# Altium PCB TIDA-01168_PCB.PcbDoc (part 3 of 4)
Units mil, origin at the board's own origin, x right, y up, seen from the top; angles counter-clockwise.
Board outline 7874.02 x 8344.02 mil, 4 copper layers (Top Layer, Signal Layer 1, Signal Layer 2, Bottom Layer), stack 65.748 mil thick; 480 components, 223 nets, 1266 pads, 1791 vias.
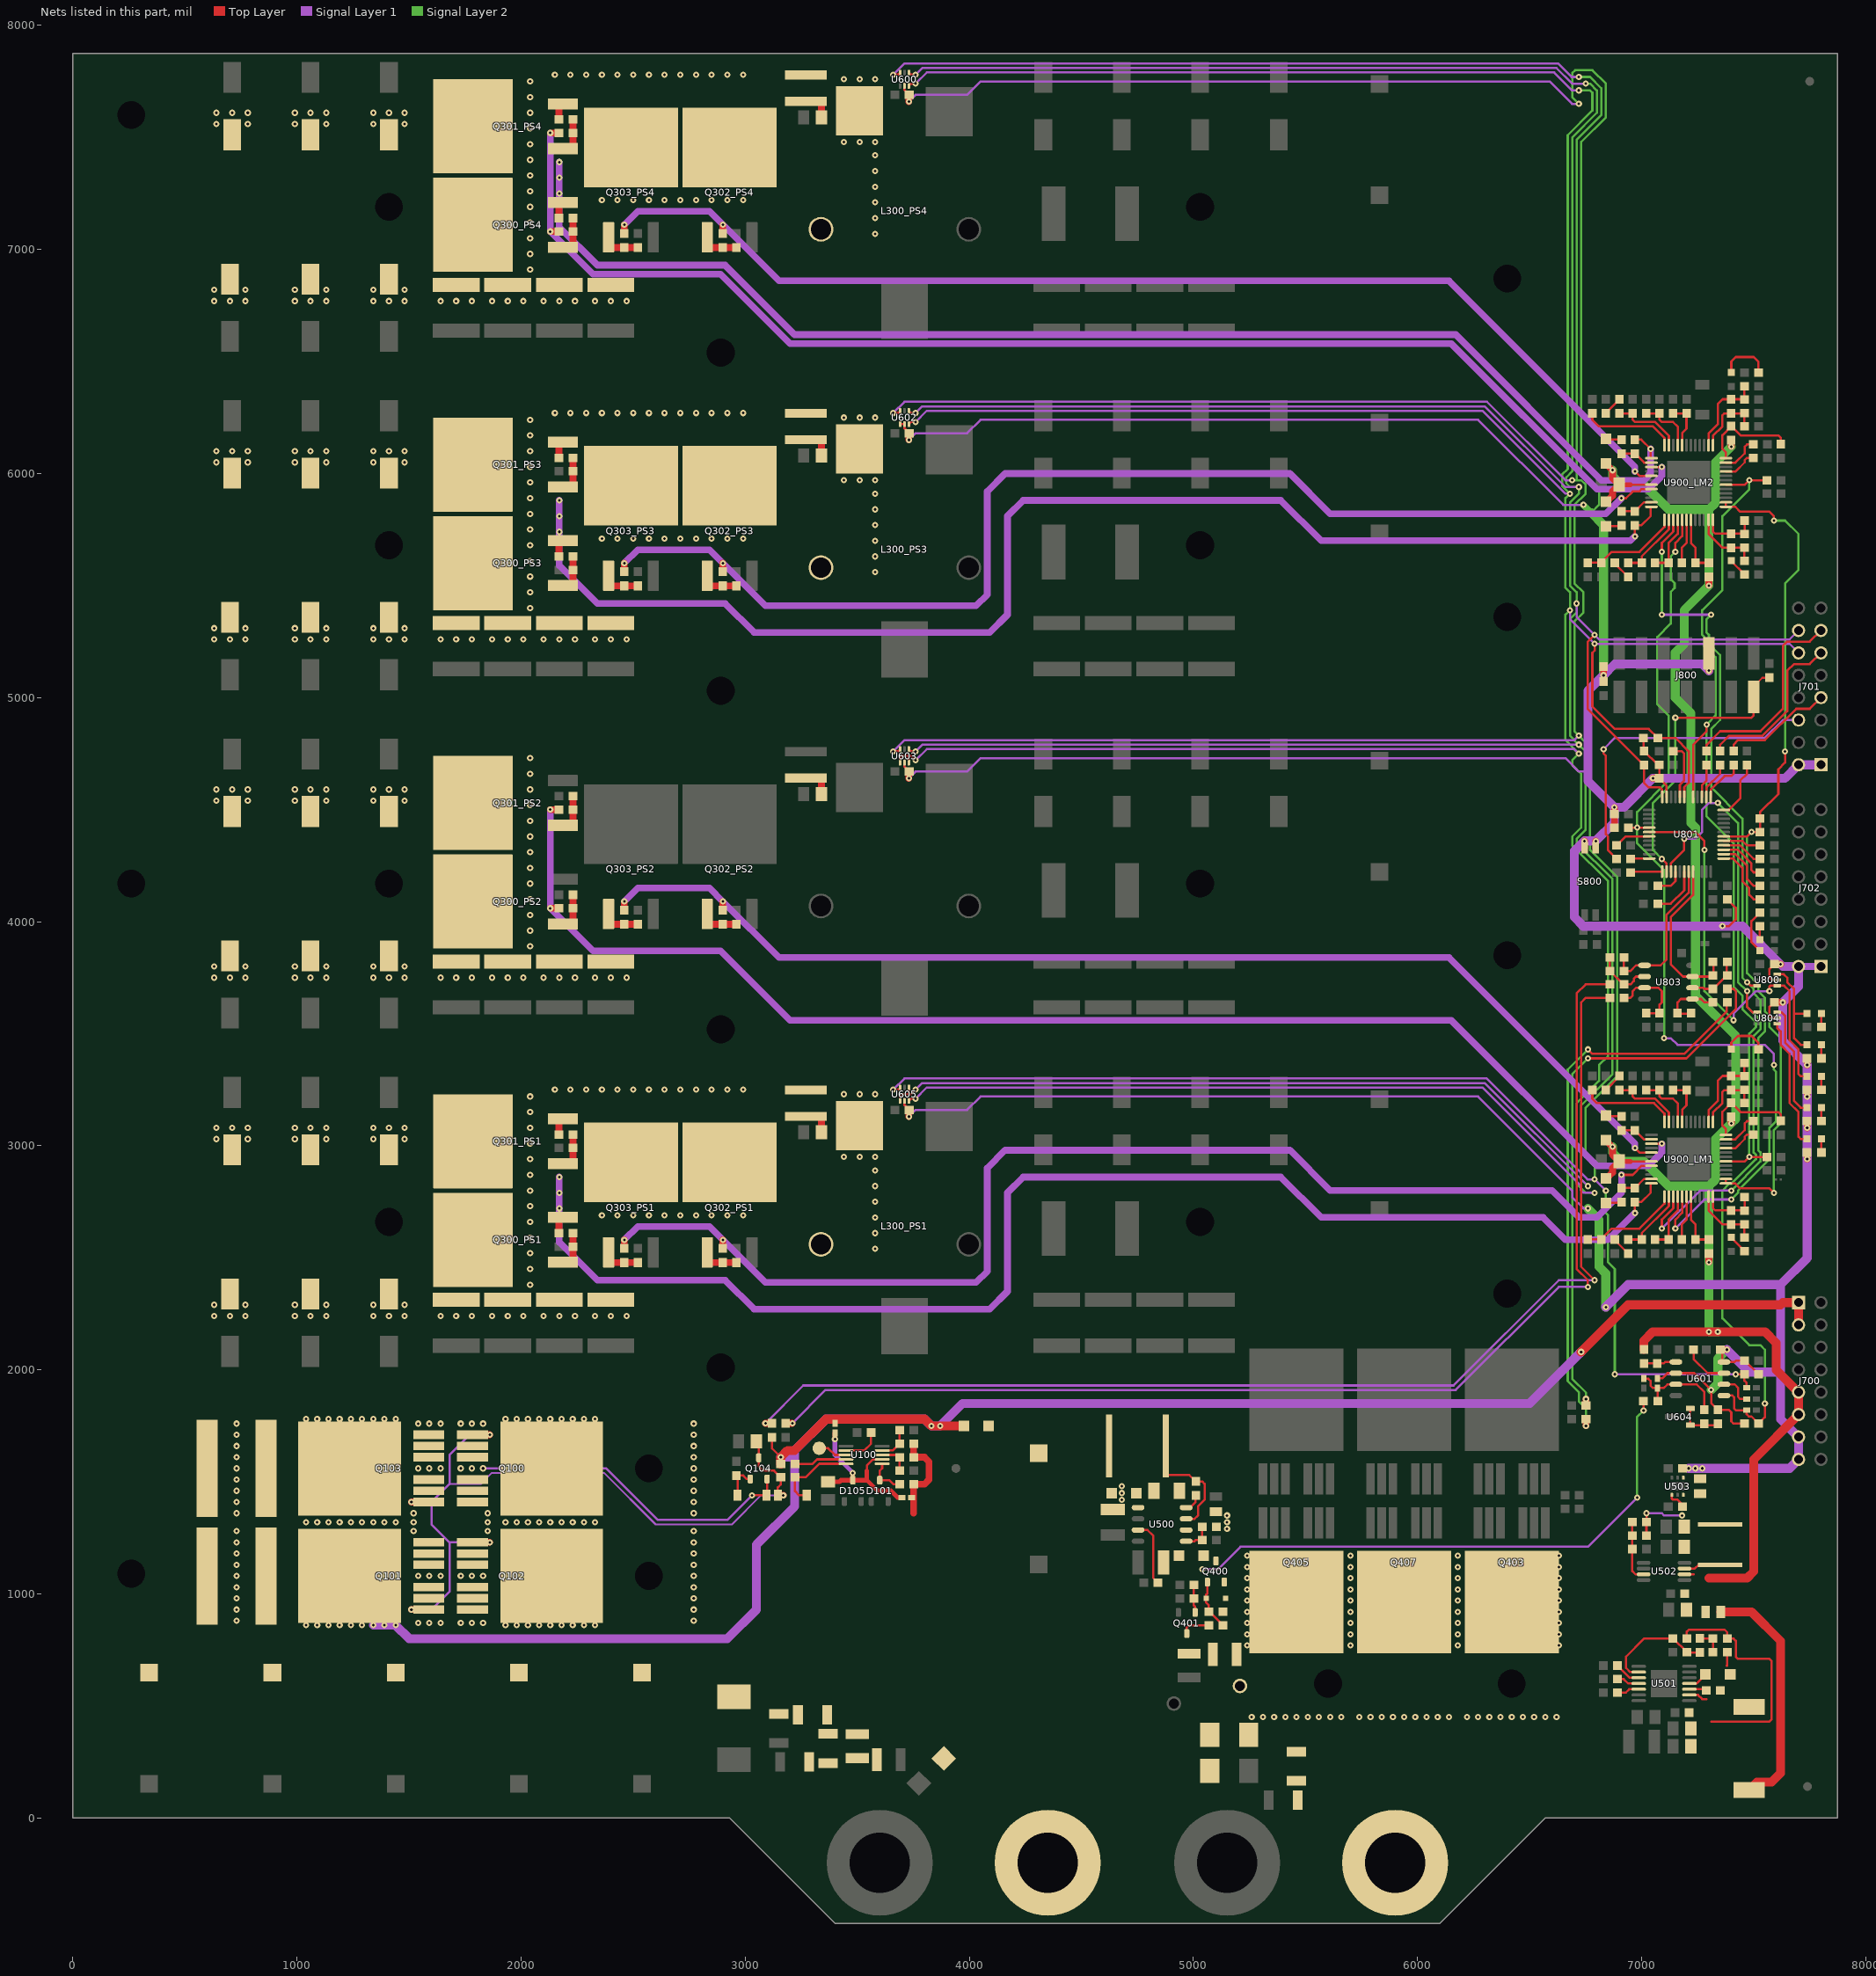
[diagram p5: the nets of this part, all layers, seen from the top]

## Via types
v1: diameter 28, hole 12, Top Layer to Bottom Layer, 1729 vias
v2: diameter 19.68, hole 7.87, Top Layer to Bottom Layer, 52 vias
v3: diameter 15.75, hole 7.87, Top Layer to Bottom Layer, 9 vias
v4: diameter 29, hole 12, Top Layer to Bottom Layer, 1 vias

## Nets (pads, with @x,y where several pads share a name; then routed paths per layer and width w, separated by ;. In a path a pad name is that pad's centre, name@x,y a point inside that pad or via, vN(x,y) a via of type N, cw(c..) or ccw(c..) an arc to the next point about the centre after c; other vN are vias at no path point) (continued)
HO2_A: R302_PS4.1 R305_PS4.1 U900_LM2.15 | length 6064.5
  Top Layer w10: U900_LM2.15@7043.66,6028.9 v1(7090,6028.9) v1@7090,6030
  Top Layer w30: v1(2130,7080) R302_PS4.1@2168.5,7080 ; v1(2130,7520) R305_PS4.1@2168.5,7520
  Signal Layer 1 w30: v1(2130,7520) v1(2130,7080) 2320,6890 2890,6890 3200,6580 6150,6580 6800,5930 7030,5930 7090,5990 v1(7090,6028.9)
HO2_B: R302_PS2.1 R305_PS2.1 U900_LM1.15 | length 6064.5
  Top Layer w10: U900_LM1.15@7043.66,3008.9 v1(7090,3008.9) v1@7090,3010
  Top Layer w30: v1(2130,4060) R302_PS2.1@2168.5,4060 ; v1(2130,4500) R305_PS2.1@2168.5,4500
  Signal Layer 1 w30: v1(2130,4500) v1(2130,4060) 2320,3870 2890,3870 3200,3560 6150,3560 6800,2910 7030,2910 7090,2970 v1(7090,3008.9)
IMON: C800.1 R804.2 U801.18 U900_LM1.37 U900_LM1.38 U900_LM2.37 U900_LM2.38 | length 3920.4
  Top Layer w10: U801.18@7366.34,4380.16 7470.16,4380.16 v1(7490,4400) R804.2@7528.5,4400 C800.1@7528.5,4460 7528.5,4488.5 7610,4570 7610,4680 7640,4710 v1(7640,4760) ; U900_LM1.38@7376.34,2851.42 U900_LM1.37@7376.34,2831.73 7418.27,2831.73 7440,2810 7570,2810 v1(7590,2790) ; U900_LM2.38@7376.34,5871.42 U900_LM2.37@7376.34,5851.73 7418.27,5851.73 7440,5830 7570,5830 7590,5810 v1(7590,5790)
  Signal Layer 2 w10: v1(7490,4400) 7470,4380 7470,3770 7520,3720 7520,3690 7550,3660 7550,3600 7570,3580 7570,3530 7620,3480 7620,3100 7590,3070 v1(7590,2790) ; v1(7590,5790) 7640,5790 7700,5730 7700,5570 7640,5510 v1(7640,4760)
ISETD: R911_LM1.2 R911_LM2.2 U801.29 U900_LM1.42 U900_LM2.42 | length 3981.4
  Top Layer w10: U801.29@7229.53,4556.34 7229.53,4789.53 7290,4850 v1(7290,4880) ; U900_LM1.42@7376.34,2930.16 7460.16,2930.16 v1(7480,2950) R911_LM1.2@7558.5,2950 ; U900_LM2.42@7376.34,5950.16 7460.16,5950.16 v1(7480,5970) R911_LM2.2@7558.5,5970
  Signal Layer 2 w10: v1(7480,2950) 7480,3500 7510,3530 7510,3550 7450,3610 7450,3670 7410,3710 7410,4349.84 7290,4469.84 v1(7290,4880) 7330,4920 7330,5180 7280,5230 7280,5270 7270,5280 7270,5390 7360,5480 7360,5810 7480,5930 v1(7480,5970)
KL30: C400.1 C401.1 D401.1 D402.1 J2.1 Q400.2 Q403.4 Q405.4 Q407.4 R400.2 RV400.2
  other v1: 5260,450 5310,450 5360,450 5410,450 5460,450 5510,450 5560,450 5610,450 5660,450 5740,450 5790,450 5840,450 5890,450 5940,450 5990,450 6040,450 6090,450 6140,450 6220,450 6270,450 6320,450 6370,450 6420,450 6470,450 6520,450 6570,450 6620,450 5240,770 5700,770 6180,770 6630,770 5240,820 5700,820 6180,820 6630,820 5240,870 5700,870 6180,870 6630,870 5240,920 5700,920 6180,920 6630,920 5240,970 5700,970 6180,970 6630,970 5240,1020 5700,1020 6180,1020 6630,1020 5240,1070 5700,1070 6180,1070 6630,1070 5240,1120 5700,1120 6180,1120 6630,1120 5240,1170 5700,1170 6180,1170 6630,1170
KL30_BIAS: C500.1 D400.1 R500.2 U500.6
KL30_M: R405.2 R831.2 | length 2528
  Top Layer w10: v1(6760,3430) 6780,3410 7190,3410 7380,3600 R831.2@7380,3640
  Top Layer w30: v1(6751.5,1750) R405.2@6751.5,1780
  Signal Layer 2 w10: v1(6751.5,1750) 6751.5,1828.5 6720,1860 6720,1900 6670,1950 6670,3340 v1(6760,3430)
KL30_POL: D400.2 Q400.3 R607.2 | length 2514.4
  Top Layer w10: v1(7008.5,1818.5) R607.2@7008.5,1860
  Signal Layer 1 w10: v1(5040,1110) 5110,1110 5210,1210 6760,1210 v1(6980,1430)
  Signal Layer 2 w10: v1(6980,1430) 6980,1790 v1(7008.5,1818.5)
KL31_M: R406.2 R829.2 | length 2479.7
  Top Layer w10: v1(6760,3390) 7200,3390 7420,3610 7420,3690 7410,3700 R829.2@7380,3700
  Top Layer w30: R406.2@6751.5,1840 v1(6751.5,1870)
  Signal Layer 2 w10: v1(6751.5,1870) 6751.5,1898.5 6690,1960 6690,3320 v1(6760,3390)
KL40: C100.1 C101.1 C102.1 D103.1 D106.2 J1.1 Q100.4 Q102.4 R100.2 R101.2 R103.2 | length 423.6
  Top Layer w30: 3751.5,1360 3751.5,1430 R103.2@3751.5,1490 3800,1490 3820,1510 3820,1590 3800,1610 R100.2@3751.5,1610 R101.2@3751.5,1670
  other v1: 1930,860 1980,860 2030,860 2080,860 2130,860 2180,860 2230,860 2280,860 2330,860 2770,880 2770,930 2770,980 2770,1030 2770,1080 2770,1130 2770,1180 2770,1230 2770,1280 1930,1320 1980,1320 2030,1320 2080,1320 2130,1320 2180,1320 2230,1320 2280,1320 2330,1320 2770,1360 2770,1410 2770,1460 2770,1510 2770,1560 2770,1610 2770,1660 2770,1710 2770,1760 1930,1780 1980,1780 2030,1780 2080,1780 2130,1780 2180,1780 2230,1780 2280,1780 2330,1780
KL40_M: R109.2 R819.2 | length 5396.1
  Top Layer w10: v1(6790,2400) 6730,2460.01 6730,3640 6750,3660 R819.2@6858.5,3660
  Top Layer w30: v1(3090,1761.5) R109.2@3120,1761.5
  Signal Layer 1 w10: v1(3090,1761.5) 3258.5,1930 6160,1930 6630,2400 v1(6790,2400)
KL41_M: R110.2 R812.2 | length 5326.3
  Top Layer w10: v1(6760,2370) 6760,2400 6710,2450 6710,3680 6750,3720 R812.2@6857.01,3720
  Top Layer w30: R110.2@3180,1761.5 v1(3210,1761.5)
  Signal Layer 1 w10: v1(3210,1761.5) 3358.5,1910 6170,1910 6630,2370 v1(6760,2370)
LO1_A: R306_PS3.2 R307_PS3.2 U900_LM2.20 | length 5423.2
  Top Layer w10: v1(6910,5890) 6930,5890 6960,5920 6990,5920 7000.47,5930.47 U900_LM2.20@7043.66,5930.47
  Top Layer w30: R307_PS3.2@2460,5561.5 v1(2460,5600) ; R306_PS3.2@2900,5561.5 v1(2900,5600)
  Signal Layer 1 w30: v1(2460,5600) 2520,5660 2840,5660 v1(2900,5600) 3090,5410 4030,5410 4080,5460 4080,5920 4160,6000 5430,6000 5610,5820 6840,5820 v1(6910,5890)
LO1_B: R306_PS1.2 R307_PS1.2 U900_LM1.20 | length 5569.5
  Top Layer w10: v1(6910,2870) 6960,2870 7000.47,2910.47 U900_LM1.20@7043.66,2910.47
  Top Layer w30: R307_PS1.2@2460,2541.5 v1(2460,2580) ; R306_PS1.2@2900,2541.5 v1(2900,2580)
  Signal Layer 1 w30: v1(2460,2580) 2520,2640 2840,2640 v1(2900,2580) 3090,2390 4030,2390 4080,2440 4080,2900 4160,2980 5430,2980 5610,2800 6600,2800 6720,2680 6800,2680 6910,2790 v1(6910,2870)
LO2_A: R306_PS4.2 R307_PS4.2 U900_LM2.17 | length 5186.2
  Top Layer w10: v1(6970,6010) 6990.47,5989.53 U900_LM2.17@7043.66,5989.53
  Top Layer w30: R307_PS4.2@2460,7071.5 v1(2460,7110) ; R306_PS4.2@2900,7071.5 v1(2900,7110)
  Signal Layer 1 w30: v1(2460,7110) 2520,7170 2840,7170 3150,6860 6140,6860 6970,6030 v1(6970,6010)
LO2_B: R306_PS2.2 R307_PS2.2 U900_LM1.17 | length 5186.2
  Top Layer w10: v1(6970,2990) 6990.47,2969.53 U900_LM1.17@7043.66,2969.53
  Top Layer w30: R307_PS2.2@2460,4051.5 v1(2460,4090) ; R306_PS2.2@2900,4051.5 v1(2900,4090)
  Signal Layer 1 w30: v1(2460,4090) 2520,4150 2840,4150 v1(2900,4090) 3150,3840 6140,3840 6970,3010 v1(6970,2990)
NetC100_2: C100.2 C103.1
NetC101_2: C101.2 C104.1
NetC102_2: C102.2 C105.1
NetC106_1: C106.1 D100.2 Q100.1 Q101.1 Q102.1 Q103.1 Q104.3 R105.1 | length 3677.7
  Top Layer w10: C106.1@3050,1680 3060,1670 Q104.3@3060,1607.24 3060,1570 3080,1550 3128.5,1550 R105.1@3158.5,1520 3158.5,1488.5 3145.53,1475.53 D100.2@3145.53,1440
  Top Layer w30: v1(1510,930) Q101.1@1587,930 ; v1(1510,1410) Q103.1@1587,1410 ; Q102.1@1783,1230 v1(1860,1230) ; Q100.1@1783,1710 v1(1860,1710) ; D100.2@3145.53,1440 v1(3170,1440)
  Signal Layer 1 w8: 1680,1490 1820,1490 1870,1540 2370,1540 2600,1310 2940,1310 3070,1440 v1(3170,1440)
  Signal Layer 1 w10: v1(1510,930) 1600,930 1680,1010 1680,1230 ; v1(1510,1410) 1600,1410 ; v1(1860,1230) 1680,1230 ; v1(1860,1710) 1770,1710 1680,1620 1680,1490 1600,1410 ; 1600,1410 1600,1310 1680,1230
NetC107_1: C107.1 D105.3 D106.1 D107.1 U100.2 | length 742.6
  Top Layer w10: 3542.76,1550 3542.76,1572.76 3570.31,1600.31 U100.2@3610.71,1600.31
  Top Layer w20: C107.1@3370,1500 3420,1500 3427.24,1507.24 3542.76,1507.24 ; v1(3400,1690) D107.1@3400,1718.35 ; D105.3@3480,1507.24 v1(3480,1540) ; 3542.76,1550 3542.76,1507.24 ; D106.1@3688.5,1430 3680,1430 3650,1460 3590,1460 3542.76,1507.24
  Signal Layer 1 w20: v1(3400,1690) 3400,1620 v1(3480,1540)
NetC108_1: C108.1 U100.7 | length 174.8
  Top Layer w10: U100.7@3449.29,1639.68 3531.18,1639.69 3561.5,1670 C108.1@3561.5,1720
NetC310_PS1_1: C310_PS1.1 R303_PS1.1 | length 140.4
  Top Layer w30: R303_PS1.1@3270,3131 3339,3131 3340,3130 C310_PS1.1@3340,3060
NetC310_PS2_1: C310_PS2.1 R303_PS2.1 | length 140.4
  Top Layer w30: R303_PS2.1@3270,4641 3339,4641 3340,4640 C310_PS2.1@3340,4570
NetC310_PS3_1: C310_PS3.1 R303_PS3.1 | length 140.4
  Top Layer w30: R303_PS3.1@3270,6151 3339,6151 3340,6150 C310_PS3.1@3340,6080
NetC310_PS4_1: C310_PS4.1 R303_PS4.1 | length 140.4
  Top Layer w30: R303_PS4.1@3270,7661 3339,7661 3340,7660 C310_PS4.1@3340,7590
NetC400_2: C400.2 C402.1
NetC401_2: C401.2 C403.1
NetC501_1: C501.1 C502.1 D500.1 D501.1 R501.1 R503.2
  other v1: 5150,1290 5150,1320 5150,1350 4680,1420 4680,1450 4680,1480
NetC503_1: C503.1 U500.3 | length 296.5
  Top Layer w10: U500.3@4752.72,1285 4795,1285 4820,1260 4820,1071.5 C503.1@4841.5,1050
NetC504_1: C504.1 U501.12 | length 101.3
  Top Layer w10: C504.1@6891.5,560 6930,560 6944.41,574.41 U501.12@6986.81,574.41
NetC505_1: C505.1 U501.3 | length 77.1
  Top Layer w10: U501.3@7213.19,574.41 7284.09,574.41 C505.1@7288.5,570
NetC505_2: C505.2 D502.1 L501.1 R508.1 U501.2 | length 146.1
  Top Layer w10: U501.2@7213.19,548.82 7251.18,548.82 7270,530 7290,530 ; 7380,680 7381.5,680 R508.1@7381.5,740
NetC508_1: C508.1 C510.1 C511.1 C512.1 L501.2 R506.1 R507.1 | length 2144.8
  Top Layer w10: R507.1@7201.5,800 7201.5,831.5 7210,840 7370,840 7381.5,828.5 C508.1@7381.5,800 7410,800 7420,790 7420,720 7430,710 7570,710 7580,700 7580,440 7570,430 7310,430
  Top Layer w40: R506.1@7353.46,920 7490,920 7620,790 7620,200 7580,160 7515.04,160 L501.2@7480,124.96
NetC508_2: C508.2 C513.2 R508.2 | length 119.1
  Top Layer w10: C513.2@7260,801.5 7261.5,800 C508.2@7318.5,800 R508.2@7318.5,740
NetC509_1: C509.1 U501.10 | length 117.9
  Top Layer w10: C509.1@6891.5,680 6945.91,625.59 U501.10@6986.81,625.59
NetC513_1: C513.1 R507.2 R509.1 U501.9 | length 503.2
  Top Layer w10: U501.9@6986.81,651.18 6948.82,651.18 6930,670 6930,720 7010,800 R507.2@7138.5,800 7141.5,800 R509.1@7201.5,740 7202.99,738.5 C513.1@7260,738.5
NetC514_1: C514.1 C517.1 C518.1 C520.1 L502.2 R510.1 R511.1 U503.4 U503.6 | length 345.5
  Top Layer w10: R511.1@7021.3,1260 C514.1@7021.3,1320 ; C514.1@7021.5,1320 v1(7021.5,1360) ; U503.4@7134.41,1441.61 7134.41,1425.59 7139,1421 7159,1421 7181.5,1398.5 C520.1@7181.5,1390
  Signal Layer 1 w10: v1(7021.5,1360) 7090,1360 7100,1350 v1(7180,1350)
NetC514_2: C514.2 R511.2 R512.1 U502.3 | length 274.4
  Top Layer w10: C514.2@6958.31,1320 6958.31,1200 6958.31,1101.5 6972.6,1087.2 U502.3@7008.27,1087.2
NetC801_1: C801.1 U801.43 | length 161.8
  Top Layer w10: C801.1@6888.5,4340 6928.66,4380.16 U801.43@7033.66,4380.16
NetC802_1: C802.1 U801.32 | length 254.4
  Top Layer w10: C802.1@7141.5,4760 7180,4760 7190,4750 7190,4630 7170.47,4610.47 U801.32@7170.47,4556.34
NetC806_1: C806.1 R812.1 R813.2 U803.2 | length 258.5
  Top Layer w10: R813.2@6857.01,3840 6857.01,3781.5 6918.5,3720 6950,3720 6965,3735 6965,3745 6975,3755 U803.2@7011.22,3755
NetC808_1: C808.1 R819.1 R822.1 U803.3 | length 370.7
  Top Layer w10: R819.1@6920,3660 6950,3660 6960,3670 6960,3690 6975,3705 7075,3705 7090,3690 7090,3640 7080,3630 C808.1@7080,3591.5 R822.1@7018.5,3591.5
NetC809_1: C809.1 R829.1 R830.2 U803.6 | length 241.8
  Top Layer w10: U803.6@7225.79,3705 7275,3705 7280,3700 7320,3700 7380,3760 7380,3818.5 C809.1@7381.5,3820
NetC810_1: C810.1 R831.1 R832.1 U803.5 | length 278.6
  Top Layer w10: R832.1@7218.5,3591.5 7217.01,3590 7160,3590 7160,3640 7175,3655 7265,3655 7280,3640 R831.1@7317.01,3640
NetC900_LM1_2: C900_LM1.2 C901_LM1.2 U900_LM1.26 | length 303.7
  Top Layer w10: C901_LM1.2@6940,2581.5 6997.01,2581.5 6998.5,2580 C900_LM1.2@7000,2581.5 7000,2610 7121.42,2731.42 U900_LM1.26@7121.42,2773.66
NetC900_LM2_2: C900_LM2.2 C901_LM2.2 U900_LM2.26 | length 303.7
  Top Layer w10: C901_LM2.2@6940,5601.5 6997.01,5601.5 6998.5,5600 C900_LM2.2@7000,5601.5 7000,5630 7121.42,5751.42 U900_LM2.26@7121.42,5793.66
NetC901_LM1_1: C901_LM1.1 R900_LM1.1 | length 87.8
  Top Layer w10: R900_LM1.1@6880,2581.5 6880,2578.5 C901_LM1.1@6940,2518.5
NetC901_LM2_1: C901_LM2.1 R900_LM2.1 | length 87.8
  Top Layer w10: R900_LM2.1@6880,5601.5 6880,5598.5 C901_LM2.1@6940,5538.5
NetC902_LM1_1: C902_LM1.1 C903_LM1.1 R901_LM1.1 U900_LM1.36 | length 257
  Top Layer w10: U900_LM1.36@7318.27,2773.66 7318.27,2721.73 7328.5,2711.5 C903_LM1.1@7400,2711.5 7458.5,2711.5 7460,2712.99 7460,2770 C902_LM1.1@7458.5,2770
NetC902_LM2_1: C902_LM2.1 C903_LM2.1 R901_LM2.1 U900_LM2.36 | length 257
  Top Layer w10: U900_LM2.36@7318.27,5793.66 7318.27,5741.73 7328.5,5731.5 C903_LM2.1@7400,5731.5 7458.5,5731.5 7460,5732.99 7460,5790 C902_LM2.1@7458.5,5790
NetC903_LM1_2: C903_LM1.2 C904_LM1.2 R904_LM1.1 U900_LM1.35 | length 307.3
  Top Layer w10: U900_LM1.35@7298.58,2773.66 7298.58,2711.42 7361.5,2648.5 C903_LM1.2@7400,2648.5 7458.5,2648.5 7458.5,2591.5 C904_LM1.2@7460,2590
NetC903_LM2_2: C903_LM2.2 C904_LM2.2 R904_LM2.1 U900_LM2.35 | length 307.3
  Top Layer w10: U900_LM2.35@7298.58,5793.66 7298.58,5731.42 7361.5,5668.5 C903_LM2.2@7400,5668.5 7458.5,5668.5 7458.5,5611.5 C904_LM2.2@7460,5610
NetC905_LM1_1: C905_LM1.1 R902_LM1.1 U900_LM1.8 | length 210.3
  Top Layer w10: C905_LM1.1@7140,3248.5 R902_LM1.1@7200,3248.5 7200,3180 7180.47,3160.47 U900_LM1.8@7180.47,3106.34
NetC905_LM2_1: C905_LM2.1 R902_LM2.1 U900_LM2.8 | length 210.3
  Top Layer w10: C905_LM2.1@7140,6268.5 R902_LM2.1@7200,6268.5 7200,6200 7180.47,6180.47 U900_LM2.8@7180.47,6126.34
NetC906_LM1_1: C906_LM1.1 R903_LM1.1 U900_LM1.28 | length 269.1
  Top Layer w10: C906_LM1.1@7060,2581.5 R903_LM1.1@7120,2581.5 7120,2670 7160.79,2710.79 U900_LM1.28@7160.79,2773.66
NetC906_LM2_1: C906_LM2.1 R903_LM2.1 U900_LM2.28 | length 269.1
  Top Layer w10: C906_LM2.1@7060,5601.5 R903_LM2.1@7120,5601.5 7120,5690 7160.79,5730.79 U900_LM2.28@7160.79,5793.66
NetC908_LM1_2: C908_LM1.2 R907_LM1.1 U900_LM1.23 | length 150.2
  Top Layer w10: R907_LM1.1@6910,2811.5 C908_LM1.2@6970,2811.5 7009.92,2851.42 U900_LM1.23@7043.66,2851.42
NetC908_LM2_2: C908_LM2.2 R907_LM2.1 U900_LM2.23 | length 150.2
  Top Layer w10: R907_LM2.1@6910,5831.5 C908_LM2.2@6970,5831.5 7009.92,5871.42 U900_LM2.23@7043.66,5871.42
NetC909_LM1_1: C909_LM1.1 R910_LM1.1 U900_LM1.31 | length 260.5
  Top Layer w10: U900_LM1.31@7219.84,2773.66 7219.84,2670.16 7240,2650 C909_LM1.1@7240,2581.5 R910_LM1.1@7300,2581.5
NetC909_LM2_1: C909_LM2.1 R910_LM2.1 U900_LM2.31 | length 260.5
  Top Layer w10: U900_LM2.31@7219.84,5793.66 7219.84,5690.16 7240,5670 C909_LM2.1@7240,5601.5 R910_LM2.1@7300,5601.5
NetC911_LM1_2: C911_LM1.2 R913_LM1.1 U900_LM1.14 | length 150.2
  Top Layer w10: R913_LM1.1@6910,3068.5 C911_LM1.2@6970,3068.5 7009.92,3028.58 U900_LM1.14@7043.66,3028.58
NetC911_LM2_2: C911_LM2.2 R913_LM2.1 U900_LM2.14 | length 146.7
  Top Layer w10: R913_LM2.1@6910,6088.5 C911_LM2.2@6970,6088.5 ; C911_LM2.2@6970,6080 6980,6080 7011.42,6048.58 U900_LM2.14@7043.66,6048.58
NetC912_LM1_1: C912_LM1.1 U900_LM1.45 | length 153.2
  Top Layer w10: U900_LM1.45@7376.34,2989.21 7419.21,2989.21 7460,3030 7460,3040 7470,3050 C912_LM1.1@7498.5,3050
NetC912_LM2_1: C912_LM2.1 U900_LM2.45 | length 153.2
  Top Layer w10: U900_LM2.45@7376.34,6009.21 7419.21,6009.21 7460,6050 7460,6060 7470,6070 C912_LM2.1@7498.5,6070
NetC913_LM1_1: C913_LM1.1 U900_LM1.12 | length 424.6
  Top Layer w10: C913_LM1.1@6780,3248.5 6780,3210 6800,3190 7054.72,3190 7101.73,3142.99 U900_LM1.12@7101.73,3106.34
NetC913_LM2_1: C913_LM2.1 U900_LM2.12 | length 416
  Top Layer w10: C913_LM2.1@6780,6268.5 6780,6240 6810,6210 7050,6210 7101.73,6158.27 U900_LM2.12@7101.73,6126.34
NetC914_LM1_1: C914_LM1.1 C915_LM1.1 R914_LM1.1 U900_LM1.2 | length 388.8
  Top Layer w10: U900_LM1.2@7298.58,3106.34 7298.58,3158.58 7340,3200 7340,3290 7361.5,3311.5 C915_LM1.1@7400,3311.5 7457.01,3311.5 R914_LM1.1@7458.5,3310 C914_LM1.1@7458.5,3370
NetC914_LM2_1: C914_LM2.1 C915_LM2.1 R914_LM2.1 U900_LM2.2 | length 388.8
  Top Layer w10: U900_LM2.2@7298.58,6126.34 7298.58,6178.58 7340,6220 7340,6310 7361.5,6331.5 C915_LM2.1@7400,6331.5 7457.01,6331.5 R914_LM2.1@7458.5,6330 C914_LM2.1@7458.5,6390
NetC915_LM1_2: C915_LM1.2 C916_LM1.2 R915_LM1.1 U900_LM1.1 | length 313.6
  Top Layer w10: U900_LM1.1@7318.27,3106.34 7318.27,3148.27 7360,3190 7360,3240 7368.5,3248.5 C915_LM1.2@7400,3248.5 7457.01,3248.5 R915_LM1.1@7458.5,3250 C916_LM1.2@7458.5,3190
NetC915_LM2_2: C915_LM2.2 C916_LM2.2 R915_LM2.1 U900_LM2.1 | length 313.6
  Top Layer w10: U900_LM2.1@7318.27,6126.34 7318.27,6168.27 7360,6210 7360,6260 7368.5,6268.5 C915_LM2.2@7400,6268.5 7457.01,6268.5 R915_LM2.1@7458.5,6270 C916_LM2.2@7458.5,6210
NetC917_LM1_1: C917_LM1.1 C920_LM1.1 U900_LM1.11 | length 321.7
  Top Layer w10: C917_LM1.1@6900,3248.5 C920_LM1.1@6960,3248.5 6960,3220 6970,3210 7060,3210 7121.42,3148.58 U900_LM1.11@7121.42,3106.34
NetC917_LM1_2: C917_LM1.2 R920_LM1.2 | length 87.8
  Top Layer w10: R920_LM1.2@6840,3248.5 6900,3308.5 C917_LM1.2@6900,3311.5
NetC917_LM2_1: C917_LM2.1 C920_LM2.1 U900_LM2.11 | length 321.7
  Top Layer w10: C917_LM2.1@6900,6268.5 C920_LM2.1@6960,6268.5 6960,6240 6970,6230 7060,6230 7121.42,6168.58 U900_LM2.11@7121.42,6126.34
NetC917_LM2_2: C917_LM2.2 R920_LM2.2 | length 87.8
  Top Layer w10: R920_LM2.2@6840,6268.5 6840,6270 6900,6330 C917_LM2.2@6900,6331.5
NetC918_LM1_1: C918_LM1.1 R918_LM1.2 U900_LM1.9 | length 264.9
  Top Layer w10: R918_LM1.2@7020,3248.5 C918_LM1.1@7080,3248.5 7080,3220 7090,3210 7140,3210 7160.79,3189.21 U900_LM1.9@7160.79,3106.34
NetC918_LM2_1: C918_LM2.1 R918_LM2.2 U900_LM2.9 | length 264.9
  Top Layer w10: R918_LM2.2@7020,6268.5 C918_LM2.1@7080,6268.5 7080,6240 7090,6230 7140,6230 7160.79,6209.21 U900_LM2.9@7160.79,6126.34
NetC919_LM1_1: C919_LM1.1 R919_LM1.2 U900_LM1.25 | length 502.4
  Top Layer w10: R919_LM1.2@6760,2581.5 R919_LM1.2@6760,2582.99 ; C919_LM1.1@6820,2581.5 C919_LM1.1@6820,2582.99 ; U900_LM1.25@7101.73,2773.66 7101.73,2741.73 6990,2630 6867.01,2630 C919_LM1.1@6820,2582.99 ; R919_LM1.2@6760,2582.99 C919_LM1.1@6820,2582.99 ; R919_LM1.2@6760,2583 C919_LM1.1@6820,2583
NetC919_LM2_1: C919_LM2.1 R919_LM2.2 U900_LM2.25 | length 440.9
  Top Layer w10: R919_LM2.2@6760,5601.5 6760,5602.99 6820,5602.99 6867.01,5650 6990,5650 7101.73,5761.73 U900_LM2.25@7101.73,5793.66
NetD100_1: D100.1 R105.2 U100.10 | length 375
  Top Layer w10: D100.1@3274.47,1440 3240,1440 3221.5,1458.5 R105.2@3221.5,1520 3270,1520 3330.63,1580.63 U100.10@3449.29,1580.63
NetD101_3: D101.3 R103.1 U100.1 | length 173.5
  Top Layer w10: U100.1@3610.71,1580.63 3610.71,1560.71 3600,1550 D101.3@3600,1507.24 3642.76,1507.24 3660,1490 R103.1@3688.5,1490
NetD102_1: D102.1 Q104.1 R106.1 | length 159.9
  Top Layer w10: D102.1@2965.53,1440 2965.53,1514.47 2960,1520 R106.1@2960,1528.5 2991.5,1528.5 3007.24,1512.76 Q104.1@3022.6,1512.76
NetD102_2: D102.2 Q100.2 Q100.3 Q100.5 Q100.6 Q100.7 Q101.2 Q101.3 Q101.5 Q101.6 Q101.7 Q102.2 Q102.3 Q102.5 Q102.6 Q102.7 Q103.2 Q103.3 Q103.5 Q103.6 Q103.7 Q104.2 | length 1479.3
  Top Layer w10: v1(3030,1440) D102.2@3094.47,1440 3097.4,1442.93 Q104.2@3097.4,1512.76
  Signal Layer 1 w10: v1(1830,1560) 2380,1560 2610,1330 2920,1330 v1(3030,1440)
  other v1: 1540,870 1590,870 1640,870 1730,870 1780,870 1830,870 1540,1080 1590,1080 1640,1080 1730,1080 1780,1080 1830,1080 1520,1280 1850,1280 1520,1320 1850,1320 1520,1360 1850,1360 1540,1560 1590,1560 1640,1560 1730,1560 1780,1560 1540,1760 1590,1760 1640,1760 1730,1760 1780,1760 1830,1760
NetD401_2: D401.2 Q400.1 R400.1 R401.2 | length 226.2
  Top Layer w10: Q400.1@5062.6,1052.76 5062.6,1002.6 5056.69,996.69 D401.2@5056.69,980 5056.69,960.82 5068.5,949.01 5068.5,922.99 R401.2@5131.5,860
NetD402_2: D402.2 D403.2
NetD501_2: D501.2 L500.2 U500.1
NetD502_2: D502.2 U501.4 | length 88.3
  Top Layer w10: U501.4@7213.19,600 7244.88,600 D502.2@7284.88,640
NetD601_1: D601.1 U601.6 | length 151.4
  Top Layer w10: U601.6@7367.28,1935 7415,1935 7430,1920 7430,1880 7440,1870 D601.1@7468.35,1870
NetD603_2: D603.2 D604.1 R606.1 R607.1 U601.3 | length 459.4
  Top Layer w10: D604.1@7010,1961.65 7011.65,1960 7030,1960 7040,1950 7040,1928.5 7050.15,1918.35 D603.2@7070,1918.35 ; R607.1@7071.5,1860 7071.5,1916.85 D603.2@7070,1918.35 ; R606.1@7280,1821.5 7280,1900 7245,1935 U601.3@7152.72,1935 7115,1935 7098.35,1918.35 D603.2@7070,1918.35
NetD700_2: D700.2 R700.2 | length 62.1
  Top Layer w10: D700.2@7528.5,3920 7527.01,3921.5 7527.01,3980 R700.2@7528.5,3980
NetD701_2: D701.2 R701.2 | length 202.8
  Top Layer w10: D701.2@7528.5,3870 7490,3908.5 7490,4002.99 7527.01,4040 R701.2@7528.5,4040
NetD800_1: D800.1 R801.1 | length 60
  Top Layer w10: R801.1@7801.5,3530 D800.1@7801.5,3590
NetD800_2: D800.2 D801.1 U800.6 | length 464
  Top Layer w10: U800.6@7604.29,3765.59 7634.41,3765.59 7650,3750 7650,3730 7680,3700 7680,3590 ; D801.1@7738.5,3450 7710,3450 7680,3480 7680,3590 ; D800.2@7738.5,3590 7680,3590
NetD801_2: D801.2 R806.1 | length 60
  Top Layer w10: R806.1@7801.5,3390 D801.2@7801.5,3450
NetD802_2: D802.2 R802.1 | length 60
  Top Layer w10: R802.1@7801.5,3250 D802.2@7801.5,3310
NetD803_1: D803.1 U804.6 | length 509.7
  Top Layer w10: U804.6@7604.29,3595.59 7624.41,3595.59 7640,3580 7640,3460 7680,3420 7680,3200 7710,3170 D803.1@7738.5,3170
NetD803_2: D803.2 R833.1 | length 60
  Top Layer w10: R833.1@7801.5,3110 D803.2@7801.5,3170
NetD804_1: D804.1 U804.4 | length 586.7
  Top Layer w10: U804.4@7604.29,3544.41 7604.29,3525.71 7620,3510 7620,3450 7660,3410 7660,3190 7700,3150 7700,3040 7710,3030 D804.1@7738.5,3030
NetD804_2: D804.2 R834.1 | length 60
  Top Layer w10: R834.1@7801.5,2970 D804.2@7801.5,3030
NetD900_LM1_1: D900_LM1.1 R907_LM1.2 | length 71.5
  Top Layer w10: D900_LM1.1@6840,2744.88 6906.38,2744.88 R907_LM1.2@6910,2748.5
NetD900_LM2_1: D900_LM2.1 R907_LM2.2 | length 71.5
  Top Layer w10: D900_LM2.1@6840,5764.88 6906.38,5764.88 R907_LM2.2@6910,5768.5
NetD901_LM1_1: D901_LM1.1 R913_LM1.2 | length 66.4
  Top Layer w10: D901_LM1.1@6843.62,3131.5 R913_LM1.2@6910,3131.5
NetD901_LM2_1: D901_LM2.1 R913_LM2.2 | length 66.4
  Top Layer w10: D901_LM2.1@6843.62,6151.5 R913_LM2.2@6910,6151.5
NetD902_LM1_2: D902_LM1.2 R916_LM1.2 | length 85.7
  Top Layer w10: D902_LM1.2@7400,2591.5 7400,2588.5 R916_LM1.2@7458.5,2530
NetD902_LM2_2: D902_LM2.2 R916_LM2.2 | length 85.7
  Top Layer w10: D902_LM2.2@7400,5611.5 7400,5608.5 R916_LM2.2@7458.5,5550
NetD903_LM1_2: D903_LM1.2 R917_LM1.2 | length 204
  Top Layer w10: D903_LM1.2@7400,3431.5 7400,3460 7430,3490 7490,3490 7521.5,3458.5 R917_LM1.2@7521.5,3430
NetD903_LM2_2: D903_LM2.2 R917_LM2.2 | length 235.7
  Top Layer w10: D903_LM2.2@7400,6451.5 7400,6500 7420,6520 7500,6520 7521.5,6498.5 R917_LM2.2@7521.5,6450
NetL500_1: L500.1 R500.1 R502.1 U500.7 | length 398.7
  Top Layer w10: L500.1@4880,1530 4981.5,1530 R502.1@5010,1501.5 5039.77,1501.5 5050,1491.27 5050,1420 5020,1390 5020,1350 5005,1335 U500.7@4967.28,1335
NetL502_1: L502.1 U502.7 | length 165.6
  Top Layer w10: U502.7@7191.34,1112.8 U502.7@7191.54,1112.8 7237.01,1112.8 7254.21,1130 L502.1@7349.8,1130
NetQ300_PS1_1: Q300_PS1.1 R301_PS1.1 R302_PS1.2 | length 128.5
  Top Layer w30: Q300_PS1.1@2231.5,2481.5 R302_PS1.2@2231.5,2550 R301_PS1.1@2231.5,2610
NetQ300_PS2_1: Q300_PS2.1 R301_PS2.1 R302_PS2.2 | length 128.5
  Top Layer w30: Q300_PS2.1@2231.5,3991.5 R302_PS2.2@2231.5,4060 R301_PS2.1@2231.5,4120
NetQ300_PS3_1: Q300_PS3.1 R301_PS3.1 R302_PS3.2 | length 128.5
  Top Layer w30: Q300_PS3.1@2231.5,5501.5 R302_PS3.2@2231.5,5570 R301_PS3.1@2231.5,5630
NetQ300_PS4_1: Q300_PS4.1 R301_PS4.1 R302_PS4.2 | length 128.5
  Top Layer w30: Q300_PS4.1@2231.5,7011.5 R302_PS4.2@2231.5,7080 R301_PS4.1@2231.5,7140
NetQ301_PS1_1: Q301_PS1.1 R304_PS1.1 R305_PS1.2 | length 174.6
  Top Layer w30: Q301_PS1.1@2186.06,2920 2230,2920 2231.5,2921.5 R305_PS1.2@2231.5,2990 R304_PS1.1@2231.5,3050
NetQ301_PS2_1: Q301_PS2.1 R304_PS2.1 R305_PS2.2 | length 174.6
  Top Layer w30: Q301_PS2.1@2186.06,4430 2230,4430 2231.5,4431.5 R305_PS2.2@2231.5,4500 R304_PS2.1@2231.5,4560
NetQ301_PS3_1: Q301_PS3.1 R304_PS3.1 R305_PS3.2 | length 174.6
  Top Layer w30: Q301_PS3.1@2186.06,5940 2230,5940 2231.5,5941.5 R305_PS3.2@2231.5,6010 R304_PS3.1@2231.5,6070
NetQ301_PS4_1: Q301_PS4.1 R304_PS4.1 R305_PS4.2 | length 174.6
  Top Layer w30: Q301_PS4.1@2186.06,7450 2230,7450 2231.5,7451.5 R305_PS4.2@2231.5,7520 R304_PS4.1@2231.5,7580
NetQ302_PS1_1: Q302_PS1.1 R306_PS1.1 R308_PS1.2 | length 128.5
  Top Layer w30: Q302_PS1.1@2831.5,2478.5 R306_PS1.1@2900,2478.5 R308_PS1.2@2960,2478.5
NetQ302_PS2_1: Q302_PS2.1 R306_PS2.1 R308_PS2.2 | length 128.5
  Top Layer w30: Q302_PS2.1@2831.5,3988.5 R306_PS2.1@2900,3988.5 R308_PS2.2@2960,3988.5
NetQ302_PS3_1: Q302_PS3.1 R306_PS3.1 R308_PS3.2 | length 128.5
  Top Layer w30: Q302_PS3.1@2831.5,5498.5 R306_PS3.1@2900,5498.5 R308_PS3.2@2960,5498.5
NetQ302_PS4_1: Q302_PS4.1 R306_PS4.1 R308_PS4.2 | length 128.5
  Top Layer w30: Q302_PS4.1@2831.5,7008.5 R306_PS4.1@2900,7008.5 R308_PS4.2@2960,7008.5
NetQ303_PS1_1: Q303_PS1.1 R307_PS1.1 R309_PS1.2 | length 128.5
  Top Layer w30: Q303_PS1.1@2391.5,2478.5 R307_PS1.1@2460,2478.5 R309_PS1.2@2520,2478.5
NetQ303_PS2_1: Q303_PS2.1 R307_PS2.1 R309_PS2.2 | length 128.5
  Top Layer w30: Q303_PS2.1@2391.5,3988.5 R307_PS2.1@2460,3988.5 R309_PS2.2@2520,3988.5
NetQ303_PS3_1: Q303_PS3.1 R307_PS3.1 R309_PS3.2 | length 128.5
  Top Layer w30: Q303_PS3.1@2391.5,5498.5 R307_PS3.1@2460,5498.5 R309_PS3.2@2520,5498.5
NetQ303_PS4_1: Q303_PS4.1 R307_PS4.1 R309_PS4.2 | length 128.5
  Top Layer w30: Q303_PS4.1@2391.5,7008.5 R307_PS4.1@2460,7008.5 R309_PS4.2@2520,7008.5
NetQ401_1: Q401.1 R402.2 R403.2 | length 125.2
  Top Layer w10: R402.2@5001.5,1040 R403.2@5001.5,980 5001.5,948.5 5007.4,942.6 Q401.1@5007.4,917.24
NetQ401_3: Q401.3 R401.1 | length 131.4
  Top Layer w10: Q401.3@4970,822.76 4970,850 4980,860 R401.1@5068.5,860 R401.1@5070,860
NetR100_1: R100.1 R107.2 U100.3 | length 141.9
  Top Layer w10: U100.3@3610.71,1620 3678.5,1620 R100.1@3688.5,1610 R107.2@3688.5,1550
NetR101_1: R101.1 R108.2 U100.4 | length 150.4
  Top Layer w10: U100.4@3610.71,1639.68 3658.19,1639.69 R101.1@3688.5,1670 R108.2@3688.5,1730
NetR104_2: R104.2 U100.9 | length 236.2
  Top Layer w10: R104.2@3221.5,1580 3300,1580 3320.31,1600.31 U100.9@3449.29,1600.31
NetR502_2: R502.2 U500.8 | length 62.5
  Top Layer w10: U500.8@4967.28,1385 4985,1385 5008.5,1408.5 R502.2@5008.5,1420
NetR503_1: R503.1 R504.2 U500.5 | length 133.3
  Top Layer w10: U500.5@4967.28,1235 5005.02,1235 5010.02,1240 R504.2@5038.5,1240 R503.1@5038.5,1300
NetR505_2: R505.2 U501.11 | length 103.6
  Top Layer w10: R505.2@6891.5,620 6920,620 6940,600 U501.11@6986.81,600
NetR602_1: R602.1 R604.2 U601.1 | length 145.4
  Top Layer w10: R602.1@7010,2028.5 R604.2@7070,2028.5 7098.5,2028.5 7105,2035 U601.1@7152.72,2035
NetR603_2: R603.2 U601.7 | length 203.6
  Top Layer w10: R603.2@7231.5,2090 7231.5,2048.5 7295,1985 U601.7@7367.28,1985
NetR605_2: R605.2 R606.2 U604.1 U604.2 | length 200
  Top Layer w10: U604.2@7217.24,1827.4 U604.1@7217.24,1752.6 7334.09,1752.6 R605.2@7340,1758.5
NetR810_2: R810.2 U801.27 | length 150.9
  Top Layer w10: U801.27@7268.9,4556.34 7268.9,4608.9 7290,4630 R810.2@7290,4698.5
NetR811_2: R811.2 U801.26 | length 167.6
  Top Layer w10: U801.26@7288.58,4556.34 7288.58,4598.58 7350,4660 R811.2@7350,4698.5
NetR814_2: R814.2 U801.24 | length 256
  Top Layer w10: U801.24@7366.34,4498.27 7388.27,4498.27 7440,4550 7440,4630 7470,4660 R814.2@7470,4698.5
NetR815_2: R815.2 U801.25 | length 201.9
  Top Layer w10: U801.25@7308.27,4556.34 7308.27,4588.27 7370,4650 7400,4650 7410,4660 R815.2@7410,4698.5
NetR816_2: R816.2 U801.48 | length 82.9
  Top Layer w10: R816.2@6951.5,4280 6953.23,4281.73 U801.48@7033.66,4281.73
NetR820_2: R820.2 U801.1 | length 143.9
  Top Layer w10: R820.2@6951.5,4220 6951.5,4223.66 U801.1@7091.73,4223.66
NetR821_1: R821.1 U801.4 | length 130.8
  Top Layer w10: R821.1@7071.5,4160 7130,4160 7150.79,4180.79 U801.4@7150.79,4223.66
NetR823_1: R823.1 U801.6 | length 227.1
  Top Layer w10: R823.1@7071.5,4080 7130,4080 7190.16,4140.16 U801.6@7190.16,4223.66
NetR824_1: R824.1 U801.13 | length 268.2
  Top Layer w10: U801.13@7388.27,4281.73 7408.27,4281.73 7450,4240 7450,4180 7480,4150 7480,4120 7500,4100 R824.1@7528.5,4100
NetR825_1: R825.1 U801.14 | length 255.9
  Top Layer w10: U801.14@7366.34,4301.42 7418.58,4301.42 7470,4250 7470,4190 7500,4160 R825.1@7528.5,4160
NetR826_1: R826.1 U801.15 | length 221.6
  Top Layer w10: U801.15@7366.34,4321.1 7428.9,4321.1 7490,4260 7490,4230 7500,4220 R826.1@7528.5,4220
NetR827_1: R827.1 U801.16 | length 187.3
  Top Layer w10: U801.16@7366.34,4340.79 7439.21,4340.79 7500,4280 R827.1@7528.5,4280
NetR828_1: R828.1 U801.17 | length 170.6
  Top Layer w10: U801.17@7366.34,4360.47 7449.53,4360.47 7470,4340 R828.1@7528.5,4340
NetR905_LM1_1: R905_LM1.1 R906_LM1.2 U900_LM1.48 | length 436.4
  Top Layer w10: U900_LM1.48@7376.34,3048.27 7376.34,3073.66 7360,3090 7360,3151.5 R905_LM1.1@7400,3191.5 7441.5,3150 7610,3150 7620,3140 R906_LM1.2@7620,3111.5
NetR905_LM2_1: R905_LM2.1 R906_LM2.2 U900_LM2.48 | length 436.4
  Top Layer w10: U900_LM2.48@7376.34,6068.27 7376.34,6093.66 7360,6110 7360,6171.5 R905_LM2.1@7400,6211.5 7441.5,6170 7610,6170 7620,6160 R906_LM2.2@7620,6131.5
NetR909_LM1_2: R909_LM1.2 U900_LM1.47 | length 173.5
  Top Layer w10: U900_LM1.47@7376.34,3028.58 7418.58,3028.58 7460,3070 7460,3100 7470,3110 R909_LM1.2@7498.5,3110
NetR909_LM2_2: R909_LM2.2 U900_LM2.47 | length 173.5
  Top Layer w10: U900_LM2.47@7376.34,6048.58 7418.58,6048.58 7460,6090 7460,6120 7470,6130 R909_LM2.2@7498.5,6130
NetR912_LM1_2: R912_LM1.2 U900_LM1.30 | length 200.5
  Top Layer w10: R912_LM1.2@7180,2581.5 7180,2650 7200.16,2670.16 U900_LM1.30@7200.16,2773.66
NetR912_LM2_2: R912_LM2.2 U900_LM2.30 | length 200.5
  Top Layer w10: R912_LM2.2@7180,5601.5 7180,5670 7200.16,5690.16 U900_LM2.30@7200.16,5793.66
NetTP100_1: TP100.1 U100.8 | length 131.7
  Top Layer w10: TP100.1@3330,1650 3370,1650 3400,1620 U100.8@3449.29,1620
NFAULT: U800.3 U900_LM1.27 U900_LM2.27 | length 4051.8
  Top Layer w10: v1(7090,2630) 7090,2670 7141.1,2721.1 U900_LM1.27@7141.1,2773.66 ; v1(7090,5650) 7090,5690 7141.1,5741.1 U900_LM2.27@7141.1,5793.66 ; v1(7470,3730) 7485.59,3714.41 U800.3@7515.71,3714.41
  Signal Layer 1 w10: v1(7090,2630) 7260,2800 v1(7400,2800) ; v1(7090,5370) v1(7310,5370)
  Signal Layer 2 w10: v1(7090,5370) v1(7090,5650) ; v1(7310,5370) 7290,5350 7290,5290 7300,5280 7300,5240 7350,5190 7350,4900 7310,4860 7310,4600 7450,4460 7450,3750 v1(7470,3730) 7500,3700 7500,3680 7530,3650 7530,3590 7550,3570 7550,3510 7520,3480 7520,2980 7530,2970 7530,2930 v1(7400,2800)
NFAULT_2: D802.1 U800.4 U801.42 | length 1899.3
  Top Layer w10: U801.42@7033.66,4399.84 7240.16,4399.84 7280,4360 v1(7280,4320) ; v1(7570,3690) 7570,3710 7574.41,3714.41 U800.4@7604.29,3714.41 7635.59,3714.41 7660,3690 7660,3470 7700,3430 7700,3320 7710,3310 D802.1@7738.5,3310
  Signal Layer 1 w10: v1(7410,3560) 7410,3590 7510,3690 v1(7570,3690)
  Signal Layer 2 w10: v1(7280,4320) 7280,3690 v1(7410,3560)
NRST: D602.1 R601.1 U601.5 U801.3 U804.1 | length 3870.5
  Top Layer w10: U801.3@7131.1,4223.66 7131.1,4261.1 7190,4320 v1(7190,4370) ; U601.5@7367.28,1885 7405,1885 7412.13,1877.87 7412.13,1827.87 7420,1820 D602.1@7468.35,1820 7468.35,1801.65 7478.43,1791.57 7489.92,1791.57 R601.1@7521.5,1760 7550,1788.5 v1(7550,1850) ; v1(7470,3690) 7470,3620 7494.41,3595.59 U804.1@7515.71,3595.59
  Signal Layer 1 w10: v1(7190,4370) 7240,4370 7270,4400 7270,4500 7300,4530 v1(7340,4530)
  Signal Layer 2 w10: v1(7340,4530) 7430,4440 7430,3730 v1(7470,3690) 7470,3620 7530,3560 7530,3520 7500,3490 7500,2970 7510,2960 7510,2940 7400,2830 7390,2830 7360,2800 7360,2230 7480,2110 7530,2110 7550,2090 v1(7550,1850)
NTRST: J800.2 R805.2 U801.2 | length 1323.3
  Top Layer w10: v1(7090,4280) 7111.42,4258.58 U801.2@7111.42,4223.66 ; v1(7150,4910) 7490,4910 7500,4920 7500,5007.43 7500,5050 7538.5,5088.5 R805.2@7570,5088.5
  Signal Layer 2 w10: v1(7090,4280) 7050,4320 7050,4530 7150,4630 v1(7150,4910)
OPT: R808.1 U801.41 U900_LM1.29 U900_LM2.29 | length 4311.6
  Top Layer w10: R808.1@6941.5,4420 v1(6980,4420) 6980.47,4419.53 U801.41@7033.66,4419.53 ; v1(7150,2630) 7150,2670 7180.47,2700.47 U900_LM1.29@7180.47,2773.66 ; v1(7150,5650) 7150,5690 7180.47,5720.47 U900_LM2.29@7180.47,5793.66
  Signal Layer 1 w10: v1(7100,3480) 7130,3480 7160,3450 7550,3450 7590,3410 v1(7590,3360) ; v1(7150,2630) 7280,2760 v1(7400,2760)
  Signal Layer 2 w10: v1(7100,3480) 7100,4230 6980,4350 v1(6980,4420) 6980,4489.53 7120,4629.53 7120,4920 7070,4970 7070,5270 7130,5330 7130,5473.13 7131.13,5473.13 7146.87,5488.87 7146.87,5511.13 7131.13,5526.87 7130,5526.87 7130,5630 v1(7150,5650) ; v1(7400,2760) 7430,2790 7430,2800 7570,2940 7570,3080 7600,3110 7600,3330 7590,3340 v1(7590,3360)
OVERTEMP: D600.1 R608.1 U600.3 U602.3 U603.3 U605.3 | length 19705.9
  Top Layer w10: v1(3660,3250) 3680.79,3250 U605.3@3690.31,3259.53 ; v1(3660,4760) 3680.79,4760 U603.3@3690.31,4769.53 ; v1(3660,6270) 3680.79,6270 U602.3@3690.31,6279.53 ; v1(3660,7780) 3680.79,7780 U600.3@3690.31,7789.53 ; v1(7420,1980) R608.1@7458.5,1980 7458.5,1951.5 7468.35,1941.65 D600.1@7468.35,1920
  Signal Layer 1 w10: v1(3660,3250) 3710,3300 6308.43,3300 6758.43,2850 v1(6790,2850) v1(6840,2800) ; v1(3660,4760) 3710,4810 6700,4810 v1(6720,4830) ; v1(3660,6270) 3710,6320 6310,6320 6660,5970 v1(6690,5970) ; v1(3660,7780) 3710,7830 6627.3,7830 6687.3,7770 v1(6720,7770) ; v1(6880,1980) v1(7420,1980)
  Signal Layer 2 w10: v1(6690,5970) 6710,5970 ; v1(6720,7770) 6770,7770 6820,7720 6820,7600 6710,7490 6710,5970 ; v1(6790,2850) 6790,2910 6750,2950 6750,3170 6890,3310 6890,4200 6770,4320 6770,4780 v1(6720,4830) 6700,4850 6700,5340 6740,5380 6740,5470 6700,5510 6700,5860 6750,5910 6750,5950 6730,5970 6710,5970 ; v1(6840,2800) 6840,2700 6850,2690 6850,2480 6880,2450 v1(6880,1980)
P3V3: C519.1 C600.1 C601.1 C602.1 C603.1 C604.1 C804.2 C805.2 C811.1 C812.1 D603.1 J700.13 J700.15 J701.1 J701.2 J702.1 J702.2 J800.5 L800.1 R510.2 R600.2 R601.2 R605.1 R608.2 R800.1 R802.2 R803.1 R806.2 R808.2 R809.2 R817.2 R818.2 R833.2 R834.2 S800.1 S800.2 U503.1 U600.5 U601.2 U601.8 U602.4 U602.5 U603.5 U605.5 U800.5 U801.35 U804.5 | length 26749.1
  Top Layer w10: U602.4@3690.31,6220.47 3710,6220.47 3710,6201.5 C601.1@3731.5,6180 ; U605.5@3710,3200.47 3710,3181.5 C603.1@3731.5,3160 ; U603.5@3710,4710.47 3710,4691.5 C602.1@3731.5,4670 C602.1@3730,4668.5 ; U600.5@3710,7730.47 3710,7711.5 C600.1@3731.5,7690 ; R818.2@7008.5,4820 7008.5,4762.99 R817.2@7010,4761.5 7071.5,4700 C805.2@7078.5,4700 C804.2@7078.5,4640 7111.42,4607.09 U801.35@7111.42,4556.34 ; D603.1@7070,1961.65 7091.65,1961.65 7115,1985 7235,1985 v1(7310,1910) 7310,1851.5 R605.1@7340,1821.5 7388.5,1821.5 7400,1810 7400,1770 7410,1760 R601.2@7458.5,1760 ; C604.1@7351.5,2090 7360,2081.5 7360,2042.28 U601.8@7367.28,2035 7415,2035 7420,2040 R600.2@7458.5,2040 7461.5,2040 R608.2@7521.5,1980 ; v1(7360,3980) 7390.08,3980 7420,4009.92 7420,4061.5 L800.1@7381.5,4100 ; C811.1@7591.5,3640 7590,3640 7570,3620 7570,3580 7580,3570 U804.5@7604.29,3570 ; C812.1@7591.5,3810 7570,3788.5 7570,3750 7580,3740 U800.5@7604.29,3740
  Top Layer w30: v1(3730,3130) 3730,3158.5 C603.1@3731.5,3160 ; v1(3730,4640) C602.1@3730,4668.5 ; v1(3730,6150) 3730,6178.5 C601.1@3731.5,6180 ; v1(3730,7660) 3730,7688.5 C600.1@3731.5,7690 ; S800.2@6745,4330 v1(6745,4360) ; S800.1@6795,4330 v1(6795,4360) ; v1(6830,5100) R800.1@6830,5138.5 ; R808.2@6878.5,4420 R809.2@6878.5,4480 v1(6878.5,4510) ; v1(7050,4640) C804.2@7078.5,4640 ; v1(7300,5120) J800.5@7300,5197.44 ; C604.1@7351.5,2090 v1(7380,2090) ; C811.1@7591.5,3640 v1(7630,3640) ; C812.1@7591.5,3810 v1(7620,3810) ; v1(7738.5,2940) R834.2@7738.5,2970 ; v1(7738.5,3080) R833.2@7738.5,3110 ; v1(7738.5,3220) R802.2@7738.5,3250 ; v1(7738.5,3360) R806.2@7738.5,3390
  Signal Layer 1 w10: v1(3730,3130) 3760,3160 3990,3160 4050,3220 6270,3220 6690,2800 6690,2770 6740,2720 v1(6760,2720) ; v1(3730,4640) 3760,4670 3990,4670 4050,4730 6660,4730 6720,4670 6760,4670 ; v1(3730,6150) 3760,6180 3990,6180 4050,6240 6270,6240 6650,5860 v1(6740,5860) ; v1(3730,7660) 3760,7690 3990,7690 4050,7750 6589.36,7750 6689.36,7650 v1(6720,7650)
  Signal Layer 1 w30: J702.2@7700,3800 J702.1@7800,3800
  Signal Layer 1 w40: v1(6840,2280) 6940,2380 7620,2380 ; v1(7210,1560) 7660,1560 J700.15@7700,1600 J700.13@7700,1700 7620,1780 7620,1990 ; v1(7300,5120) 7270,5150 6880,5150 v1(6830,5100) 6760,5030 6760,4670 6760,4628.5 v1(6878.5,4510) ; v1(7380,2090) 7480,1990 7620,1990 ; J701.1@7800,4700 J701.2@7700,4700 7640,4640 v1(7050,4640) 6920,4510 v1(6878.5,4510) ; v1(6878.5,4510) 6878.5,4443.5 v1(6795,4360) v1(6745,4360) 6700,4315 6700,4020 6740,3980 v1(7360,3980) 7450,3980 v1(7620,3810) 7630,3800 J702.2@7700,3800 7700,3710 v1(7630,3640) 7630,3468.5 v1(7738.5,3360) v1(7738.5,3220) v1(7738.5,3080) v1(7738.5,2940) 7738.5,2498.5 7620,2380 ; 7620,1990 7620,2380
  Signal Layer 2 w10: v1(6720,7650) 6690,7680 6690,7787.3 6702.7,7800 6780,7800 6840,7740 6840,7590 6730,7480 6730,6000 6810,5920 6810,5860 6775,5825 6770,5820
  Signal Layer 2 w30: v1(6740,5860) 6775,5825
  Signal Layer 2 w40: v1(6760,2720) 6810,2670 6810,2460 6840,2430 v1(6840,2280) ; 6775,5825 6830,5770 v1(6830,5100) ; v1(7310,1910) 7340,1940 7340,2050 v1(7380,2090)
  other v1: 7240,1560 7270,1560
P10V: C515.1 C516.2 C910_LM1.1 C910_LM2.1 D900_LM1.2 D900_LM2.2 D901_LM1.2 D901_LM2.2 J700.9 J700.11 R506.2 R602.2 R905_LM1.2 R905_LM2.2 R910_LM1.2 R910_LM2.2 U502.6 U900_LM1.19 U900_LM2.19 | length 8219.3
  Top Layer w10: 6950,2930 6950.16,2930.16 U900_LM1.19@7043.66,2930.16 ; 6950,5950 6950.16,5950.16 U900_LM2.19@7043.66,5950.16 ; U502.6@7191.34,1087.2 U502.6@7191.54,1087.2 7232.6,1087.2
  Top Layer w20: C910_LM1.1@6900,2930 6950,2930 ; C910_LM2.1@6900,5950 6950,5950
  Top Layer w30: D900_LM1.2@6840,2855.12 6845.11,2855.11 6870,2880 6870,2900 C910_LM1.1@6900,2930 6870,2960 v1(6870,2994.88) D901_LM1.2@6840,3024.88 ; D900_LM2.2@6840,5875.12 6845.11,5875.11 6870,5900 6870,5920 C910_LM2.1@6900,5950 6870,5980 v1(6870,6014.88) D901_LM2.2@6840,6044.88 ; v1(7300,2480) R910_LM1.2@7300,2518.5 ; v1(7300,5500) R910_LM2.2@7300,5538.5 ; v1(7400,3100) R905_LM1.2@7400,3128.5 ; v1(7400,6120) R905_LM2.2@7400,6148.5
  Top Layer w40: R602.2@7010,2091.5 7010,2130 7050,2170 v1(7300,2170) v1(7340,2170) 7550,2170 7600,2120 7600,2000 J700.9@7700,1900 J700.11@7700,1800 7500,1600 7500,1100 7470,1070 7300,1070
  Signal Layer 2 w40: v1(6870,2994.88) 6870,2970 6910,2930 7010,2930 7120,2820 7300,2820 ; v1(6870,6014.88) 6870,5990 6910,5950 7010,5950 7120,5840 7300,5840 ; v1(7340,2170) v1(7300,2170) v1(7300,2480) 7300,2820 ; v1(7400,6120) 7330,6050 7330,5870 7300,5840 ; 7300,2820 7330,2850 7330,3030 v1(7400,3100) 7420,3120 7420,3490 7240,3670 7240,4420 7220,4440 7220,4930 7150,5000 7150,5200 7190,5240 7190,5390 v1(7300,5500) 7300,5840
P12V_MEAS: C809.2 R830.1 U801.8 U803.7 | length 728.6
  Top Layer w10: U801.8@7229.53,4223.66 7229.53,4119.53 7130,4020 7130,3810 7185,3755 7312.01,3755 7320,3762.99 7320,3818.5 C809.2@7318.5,3820
P48V: C200.1 C201.1 C202.1 C203.1 C204.1 D104.1 D107.2 D500.2 J700.1 J700.3 L200.1 L201.1 Q101.4 Q103.4 R104.1 R109.1 | length 8542.5
  Top Layer w10: R109.1@3120,1698.5 3120,1648.5 v1(3158.5,1610)
  Top Layer w40: R104.1@3158.5,1580 v1(3158.5,1610) 3188.5,1640 3220,1640 3360,1780 3800,1780 v1(3830,1750) v1(3870,1750) D500.2@3974.88,1750 ; v1(6730,2080) 6940,2290 7620,2290 7630,2300 J700.1@7700,2300 J700.3@7700,2200
  Signal Layer 1 w40: v1(1340,860) v1(1390,860) v1(1440,860) 1500,800 2920,800 3050,930 3050,1220 3220,1390 3220,1640 3360,1780 3800,1780 v1(3830,1750) v1(3870,1750) 3970,1850 6500,1850 v1(6730,2080) ; v1(3158.5,1610) 3220,1610
  other v1: 1040,860 1090,860 1140,860 1190,860 1240,860 1290,860 730,880 730,930 730,980 730,1030 730,1080 730,1130 730,1180 730,1230 730,1280 1040,1320 1090,1320 1140,1320 1190,1320 1240,1320 1290,1320 1340,1320 1390,1320 1440,1320 730,1360 730,1410 730,1460 730,1510 730,1560 730,1610 730,1660 730,1710 730,1760 1040,1780 1090,1780 1140,1780 1190,1780 1240,1780 1290,1780 1340,1780 1390,1780 1440,1780
P48V_MEAS: C806.2 R813.1 U801.7 U803.1 | length 705.7
  Top Layer w10: R813.1@6920,3840 6920,3780 6950,3780 6975,3805 7085,3805 7110,3830 7110,4030 7209.84,4129.84 U801.7@7209.84,4223.66
P48V_NF: C300_PS1.1 C300_PS2.1 C300_PS3.1 C300_PS4.1 C301_PS1.1 C301_PS2.1 C301_PS3.1 C301_PS4.1 C302_PS1.1 C302_PS2.1 C302_PS3.1 C302_PS4.1 C303_PS1.1 C303_PS2.1 C303_PS3.1 C303_PS4.1 C304_PS1.1 C304_PS2.1 C304_PS3.1 C304_PS4.1 C311_PS1.1 C311_PS2.1 C311_PS3.1 C311_PS4.1 C312_PS1.1 C312_PS2.1 C312_PS3.1 C312_PS4.1 C313_PS1.1 C313_PS2.1 C313_PS3.1 C313_PS4.1 C314_PS1.1 C314_PS2.1 C314_PS3.1 C314_PS4.1 C315_PS1.1 C315_PS2.1 C315_PS3.1 C315_PS4.1 L200.2 L201.2 Q300_PS1.4 Q300_PS2.4 Q300_PS3.4 Q300_PS4.4 Q301_PS1.4 Q301_PS2.4 Q301_PS3.4 Q301_PS4.4
  other v1: 630,2240 700,2240 770,2240 990,2240 1060,2240 1130,2240 1340,2240 1410,2240 1480,2240 1640,2240 1710,2240 1780,2240 1870,2240 1940,2240 2010,2240 2100,2240 2170,2240 2240,2240 2330,2240 2400,2240 2470,2240 630,2290 770,2290 990,2290 1130,2290 1340,2290 1480,2290 2040,2380 2040,2450 2040,2520 2040,2590 2040,2660 2040,2730 2040,2800 2040,2870 2040,2940 2040,3010 640,3030 780,3030 990,3030 1130,3030 1340,3030 1480,3030 640,3080 710,3080 780,3080 990,3080 1060,3080 1130,3080 1340,3080 1410,3080 1480,3080 2040,3080 2040,3150 2040,3220 630,3750 700,3750 770,3750 990,3750 1060,3750 1130,3750 1340,3750 1410,3750 1480,3750 1640,3750 1710,3750 1780,3750 1870,3750 1940,3750 2010,3750 2100,3750 2170,3750 2240,3750 2330,3750 2400,3750 2470,3750 630,3800 770,3800 990,3800 1130,3800 1340,3800 1480,3800 2040,3890 2040,3960 2040,4030 2040,4100 2040,4170 2040,4240 2040,4310 2040,4380 2040,4450 2040,4520 640,4540 780,4540 990,4540 1130,4540 1340,4540 1480,4540 640,4590 710,4590 780,4590 990,4590 1060,4590 1130,4590 1340,4590 1410,4590 1480,4590 2040,4590 2040,4660 2040,4730 630,5260 700,5260 770,5260 990,5260 1060,5260 1130,5260 1340,5260 1410,5260 1480,5260 1640,5260 1710,5260 1780,5260 1870,5260 1940,5260 2010,5260 2100,5260 2170,5260 2240,5260 2330,5260 2400,5260 2470,5260 630,5310 770,5310 990,5310 1130,5310 1340,5310 1480,5310 2040,5400 2040,5470 2040,5540 2040,5610 2040,5680 2040,5750 2040,5820 2040,5890 2040,5960 2040,6030 640,6050 780,6050 990,6050 1130,6050 1340,6050 1480,6050 640,6100 710,6100 780,6100 990,6100 1060,6100 1130,6100 1340,6100 1410,6100 1480,6100 2040,6100 2040,6170 2040,6240 630,6770 700,6770 770,6770 990,6770 1060,6770 1130,6770 1340,6770 1410,6770 1480,6770 1640,6770 1710,6770 1780,6770 1870,6770 1940,6770 2010,6770 2100,6770 2170,6770 2240,6770 2330,6770 2400,6770 2470,6770 630,6820 770,6820 990,6820 1130,6820 1340,6820 1480,6820 2040,6910 2040,6980 2040,7050 2040,7120 2040,7190 2040,7260 2040,7330 2040,7400 2040,7470 2040,7540 640,7560 780,7560 990,7560 1130,7560 1340,7560 1480,7560 640,7610 710,7610 780,7610 990,7610 1060,7610 1130,7610 1340,7610 1410,7610 1480,7610 2040,7610 2040,7680 2040,7750
RXD: J701.6 R816.1 | length 1438.1
  Top Layer w10: v1(6830,4770) 6830,4750 6840,4740 6840,4390 6850,4380 6850,4318.5 R816.1@6888.5,4280
  Signal Layer 1 w10: v1(6830,4770) 6880,4820 7550,4820 7630,4900 J701.6@7700,4900
SCL: J701.14 R817.1 U600.1 U602.1 U603.1 U605.1 U605.4 U801.36 | length 19853.2
  Top Layer w10: U605.4@3690.31,3200.47 3690.31,3220.31 3700,3230 3730,3230 ; U605.1@3729.68,3259.53 3729.68,3230.32 3730,3230 ; U603.1@3729.68,4769.53 3739.21,4760 v1(3760,4760) ; U602.1@3729.68,6279.53 3739.21,6270 v1(3760,6270) ; U600.1@3729.68,7789.53 3739.21,7780 v1(3760,7780) ; v1(3760,3250) 3740,3230 3730,3230 ; v1(6790,5280) 6760,5250 6760,4948.5 R817.1@7010,4698.5 7010,4620 7030,4600 7080,4600 7091.73,4588.27 U801.36@7091.73,4556.34
  Signal Layer 1 w10: v1(3760,3250) 3790,3280 6300,3280 v1(6760,2820) ; v1(3760,4760) 3790,4790 v1(6720,4790) ; v1(3760,6270) 3790,6300 6300,6300 6660,5940 v1(6720,5940) ; v1(3760,7780) 3790,7810 6620,7810 6690,7740 v1(6750,7740) ; v1(6710,5420) 6710,5360 v1(6790,5280) 6810,5260 7660,5260 J701.14@7700,5300
  Signal Layer 2 w10: v1(6750,7740) 6770,7740 6800,7710 6800,7610 6690,7500 6690,6010 6663.13,5983.13 6663.13,5956.87 6680,5940 v1(6720,5940) 6720,5910 6680,5870 6680,5500 6710,5470 v1(6710,5420) 6710,5380 6680,5350 6680,4830 v1(6720,4790) 6750,4760 6750,4410 6710,4370 6710,4350 6870,4190 6870,3320 6730,3180 6730,2850 v1(6760,2820)
SDA: J701.12 R818.1 U600.6 U602.6 U603.4 U603.6 U605.6 U801.31 | length 20039.5
  Top Layer w10: U603.4@3690.31,4710.47 3690.31,4730.31 3700,4740 3729.68,4740 ; U605.6@3729.68,3200.47 3739.21,3210 v1(3760,3210) ; U603.6@3729.68,4710.47 3729.68,4740 ; U602.6@3729.68,6220.47 3739.21,6230 v1(3760,6230) ; U600.6@3729.68,7730.47 3739.21,7740 v1(3760,7740) ; v1(3760,4720) 3740,4740 3729.68,4740 ; v1(6790,5240) 6790,5210 6780,5200 6780,4960 6880,4860 7031.5,4860 R818.1@7071.5,4820 7150,4820 7210,4760 7210,4620 7190.16,4600.16 U801.31@7190.16,4556.34
  Signal Layer 1 w10: v1(3760,3210) 3810,3260 6290,3260 6728.43,2821.57 6728.43,2801.57 6740,2790 v1(6790,2790) ; v1(3760,4720) 3810,4770 6700,4770 v1(6720,4750) ; v1(3760,6230) 3810,6280 6290,6280 6660,5910 v1(6680,5910) ; v1(3760,7740) 3810,7790 6610,7790 6690,7710 v1(6720,7710) ; v1(6680,5390) 6680,5350 v1(6790,5240) 7660,5240 J701.12@7700,5200
  Signal Layer 2 w10: v1(6720,7710) 6770,7710 6780,7700 6780,7620 6670,7510 6670,6020 6645.25,5995.25 6645.25,5944.75 v1(6680,5910) 6660,5890 6660,5490 6680,5470 v1(6680,5390) 6660,5370 6660,4810 v1(6720,4750) 6690,4720 6690,4700 6730,4660 6730,4420 6690,4380 6690,4340 6850,4180 6850,3400 6810,3360 6810,3290 6710,3190 6710,2830 6750,2790 v1(6790,2790)
SIMO: J701.13 R810.1 | length 913.8
  Top Layer w10: R810.1@7290,4761.5 7290,4790 7350,4850 7530,4850 7630,4950 7630,5230 7650,5250 7750,5250 J701.13@7800,5300
SOMI: J701.11 R811.1 | length 753.8
  Top Layer w10: R811.1@7350,4761.5 7350,4790 7390,4830 7540,4830 7650,4940 7650,5120 7680,5150 7750,5150 J701.11@7800,5200
STEA: J701.7 R815.1 | length 505.5
  Top Layer w10: R815.1@7410,4761.5 7410,4790 7430,4810 7550,4810 7690,4950 7750,4950 J701.7@7800,5000
SW1_A: C908_LM2.1 L300_PS3.2 Q300_PS3.3 Q301_PS3.3 Q302_PS3.4 Q303_PS3.4 R301_PS3.2 R303_PS3.2 R304_PS3.2 U900_LM2.24 | length 6107.9
  Top Layer w10: v1(6970,5720) C908_LM2.1@6970,5768.5 6998.5,5768.5 7040,5810 7040,5848.07 U900_LM2.24@7043.66,5851.73
  Top Layer w30: R301_PS3.2@2168.5,5630 Q300_PS3.3@2168.5,5682.44 ; R304_PS3.2@2168.5,6070 2168.5,6122.44 Q301_PS3.3@2186.06,6140
  Signal Layer 1 w30: v1(2170,5880) v1(2170,5810) v1(2170,5740) 2170,5590 2340,5420 2910,5420 3040,5290 4090,5290 4170,5370 4170,5810 4240,5880 5390,5880 5570,5700 6950,5700 v1(6970,5720)
  other v1: 3580,5560 3580,5630 3580,5700 2360,5710 2430,5710 2500,5710 2570,5710 2640,5710 2710,5710 2780,5710 2850,5710 2920,5710 2990,5710 3580,5770 3580,5840 3580,5910 3440,5970 3510,5970 3580,5970 3440,6250 3510,6250 3580,6250 2150,6270 2220,6270 2290,6270 2360,6270 2430,6270 2500,6270 2570,6270 2640,6270 2710,6270 2780,6270 2850,6270 2920,6270 2990,6270
SW1_B: C908_LM1.1 L300_PS1.2 Q300_PS1.3 Q301_PS1.3 Q302_PS1.4 Q303_PS1.4 R301_PS1.2 R303_PS1.2 R304_PS1.2 U900_LM1.24 | length 6190.7
  Top Layer w10: v1(6970,2700) C908_LM1.1@6970,2748.5 6998.5,2748.5 7040,2790 7040,2828.07 U900_LM1.24@7043.66,2831.73
  Top Layer w30: R301_PS1.2@2168.5,2610 Q300_PS1.3@2168.5,2662.44 ; R304_PS1.2@2168.5,3050 2168.5,3102.44 Q301_PS1.3@2186.06,3120
  Signal Layer 1 w30: v1(2170,2860) v1(2170,2790) v1(2170,2720) 2170,2570 2340,2400 2910,2400 3040,2270 4090,2270 4170,2350 4170,2790 4240,2860 5390,2860 5570,2680 6560,2680 6660,2580 6850,2580 v1(6970,2700)
  other v1: 3580,2540 3580,2610 3580,2680 2360,2690 2430,2690 2500,2690 2570,2690 2640,2690 2710,2690 2780,2690 2850,2690 2920,2690 2990,2690 3580,2750 3580,2820 3580,2890 3440,2950 3510,2950 3580,2950 3440,3230 3510,3230 3580,3230 2150,3250 2220,3250 2290,3250 2360,3250 2430,3250 2500,3250 2570,3250 2640,3250 2710,3250 2780,3250 2850,3250 2920,3250 2990,3250
SW2_A: C911_LM2.1 L300_PS4.2 Q300_PS4.3 Q301_PS4.3 Q302_PS4.4 Q303_PS4.4 R301_PS4.2 R303_PS4.2 R304_PS4.2 U900_LM2.13 | length 6010.6
  Top Layer w10: C911_LM2.1@6970,6151.5 6998.5,6151.5 v1(7040,6110) 7040,6071.93 U900_LM2.13@7043.66,6068.27
  Top Layer w30: R301_PS4.2@2168.5,7140 Q300_PS4.3@2168.5,7192.44 ; R304_PS4.2@2168.5,7580 2168.5,7632.44 Q301_PS4.3@2186.06,7650
  Signal Layer 1 w30: v1(2170,7390) v1(2170,7320) v1(2170,7250) 2170,7100 2340,6930 2910,6930 3220,6620 6170,6620 6820,5970 7010,5970 7040,6000 v1(7040,6110)
  other v1: 3580,7070 3580,7140 3580,7210 2360,7220 2430,7220 2500,7220 2570,7220 2640,7220 2710,7220 2780,7220 2850,7220 2920,7220 2990,7220 3580,7280 3580,7350 3580,7420 3440,7480 3510,7480 3580,7480 3440,7760 3510,7760 3580,7760 2150,7780 2220,7780 2290,7780 2360,7780 2430,7780 2500,7780 2570,7780 2640,7780 2710,7780 2780,7780 2850,7780 2920,7780 2990,7780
